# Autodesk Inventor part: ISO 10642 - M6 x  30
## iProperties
Comments: To add or edit properties for Autodesk Inventor files, use iProperties.
Created: 2005-06
Part Number: ISO 10642 - M6 x  30
Vendor: Autodesk Inc.
Document SubType Name: Modeling
Designer: John Blackburn
Material: Default
Description: Hexagon Socket Countersunk Head Screw
Standard: ISO 10642
Alert: To add or edit properties for Autodesk Inventor files, use iProperties.
Control State: 0
Master: False
Checked Out: False
Shininess: 64.0
Length Units: 11269
Angle Units: 11279
Time Units: 11290
Mass Units: 11283
Length Display Precision: 3
Angle Display Precision: 2
Compacted: True
EGR: 1
Density: 0.0
Volumn: 0.0
Area: 0.0
PropertySet Name: Model Information
Author: John Blackburn
Revision Number: 8
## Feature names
1. Body [Revolution]
2. Slot [Extrusion]
3. Chamfer1
